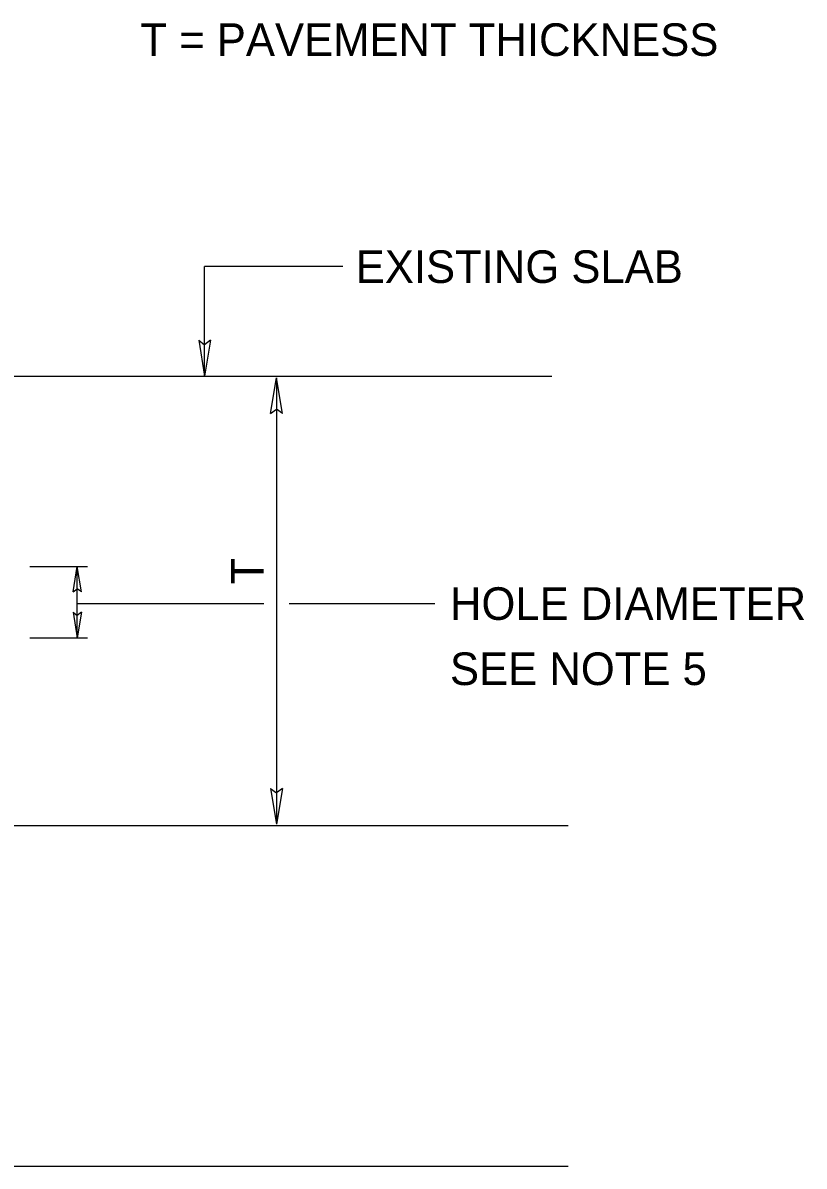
# Model space of a CAD drawing. Extents: x 2.92 to 10.05, y 1.3 to 10.63.
# Drawn here: x 6.873 to 8.31, y 5.922 to 8.026 of the extents above; entities that cross this region are included whole.
import ezdxf

# ---------------------------------------------------------------- set-up
doc = ezdxf.new("R2010")
doc.units = 0
for name, color, linetype in [('DETL-DIMS', 7, 'Continuous'), ('DETL-LINE', 7, 'Continuous'), ('DETL-NOTE', 7, 'Continuous')]:
    doc.layers.add(name, color=color, linetype=linetype)

msp = doc.modelspace()

# ---------------------------------------------------------------- linework, layer by layer
at = {"layer": 'DETL-DIMS'}
for p, q in [((7.4615, 7.5776), (7.2071, 7.5776)), ((7.2071, 7.3763), (7.2071, 7.5776)), ((7.1961, 7.4422), (7.2071, 7.3763)), ((7.1961, 7.4422), (7.2071, 7.4339)), ((7.218, 7.4422), (7.2071, 7.3763)), ((7.218, 7.4422), (7.2071, 7.4339)), ((7.3284, 7.3073), (7.3393, 7.3731)), ((7.3393, 7.3731), (7.3393, 6.5513)), ((7.3503, 7.3073), (7.3393, 7.3731)), ((7.3284, 7.3073), (7.3393, 7.3155)), ((7.3503, 7.3073), (7.3393, 7.3155)), ((6.8855, 7.0258), (6.9916, 7.0258)), ((6.965, 6.9787), (6.9728, 7.0258)), ((6.9807, 6.9787), (6.9728, 7.0258)), ((6.9728, 6.8942), (6.9728, 7.0258)), ((6.965, 6.9787), (6.9728, 6.9846)), ((6.9807, 6.9787), (6.9728, 6.9846)), ((6.9728, 6.9573), (7.3157, 6.9573)), ((7.3627, 6.9573), (7.6304, 6.9573)), ((6.965, 6.9412), (6.9728, 6.8942)), ((6.965, 6.9412), (6.9728, 6.9353)), ((6.9807, 6.9412), (6.9728, 6.8942)), ((6.9807, 6.9412), (6.9728, 6.9353)), ((6.8855, 6.8942), (6.9916, 6.8942)), ((7.3284, 6.6171), (7.3393, 6.5513)), ((7.3284, 6.6171), (7.3393, 6.6089)), ((7.3503, 6.6171), (7.3393, 6.5513)), ((7.3503, 6.6171), (7.3393, 6.6089))]:
    msp.add_line(p, q, dxfattribs=at)
at = {"layer": 'DETL-LINE'}
for p, q in [((5.6014, 7.3763), (7.8456, 7.3763)), ((3.6014, 6.549), (7.8761, 6.549)), ((3.6014, 5.9216), (7.8761, 5.9216))]:
    msp.add_line(p, q, dxfattribs=at)

# ---------------------------------------------------------------- texts
at = {"layer": 'DETL-NOTE'}
for s, p in [('T = PAVEMENT THICKNESS', (7.089, 7.9656)), ('EXISTING SLAB', (7.485, 7.5476)), ('HOLE DIAMETER ', (7.6584, 6.9273)), ('SEE NOTE 5', (7.6584, 6.8073))]:
    msp.add_text(s, height=0.06, dxfattribs=at).set_placement(p)
msp.add_text('T', height=0.06, rotation=90, dxfattribs=at).set_placement((7.3157, 6.9925))

doc.saveas('drawing.dxf')
